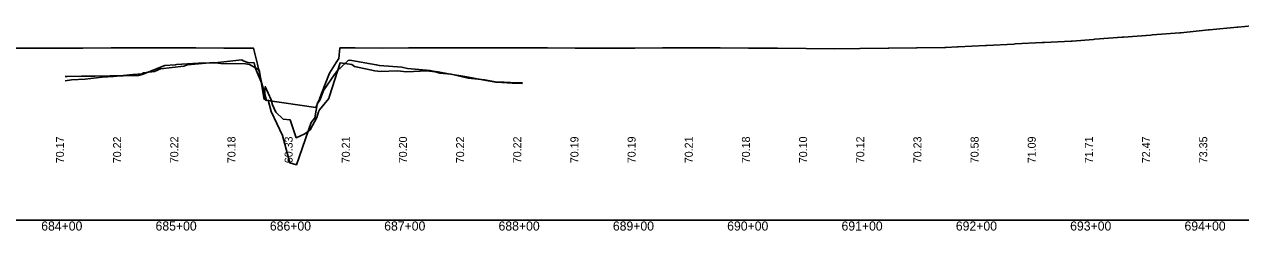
# Model space of a CAD drawing. Extents: x 2526761 to 2530854, y 882903 to 888012.
# Drawn here: x 2528703 to 2529767, y 887503 to 887684 of the extents above; entities that cross this region are included whole.
import ezdxf

# ---------------------------------------------------------------- set-up
doc = ezdxf.new("R2010")
doc.units = 0
for name, color, linetype in [('RD_DDB_Profile_EX', 7, 'Continuous'), ('RD_DDB_StaTX', 7, 'Continuous'), ('RD_DDB_StripGrade', 7, 'Continuous'), ('RD_GPK_Profile_Cell', 7, 'Continuous')]:
    doc.layers.add(name, color=color, linetype=linetype)

msp = doc.modelspace()

# ---------------------------------------------------------------- linework, layer by layer
at = {"layer": 'RD_DDB_Profile_EX'}
for points in [[(2529311.6, 887663.2), (2529312.1, 887663.2), (2529336.7, 887663), (2529337.1, 887663), (2529361.8, 887662.8), (2529362.1, 887662.8), (2529387.1, 887662.6), (2529412.1, 887662.4), (2529434.1, 887662.6), (2529434.4, 887662.6), (2529458.9, 887662.9), (2529459.4, 887662.9), (2529483.8, 887663.2), (2529484.4, 887663.2), (2529508.6, 887663.4), (2529509.4, 887663.5), (2529519.6, 887664), (2529520.1, 887664), (2529544, 887665.2), (2529545.1, 887665.3), (2529568.9, 887666.5), (2529570.1, 887666.6), (2529593.7, 887667.8), (2529595.2, 887667.9), (2529595.7, 887667.9), (2529619.1, 887669.1), (2529619.9, 887669.2), (2529638.5, 887670.6), (2529639.8, 887670.7), (2529663.5, 887672.5), (2529664.7, 887672.6), (2529688.8, 887674.4), (2529689.7, 887674.5), (2529714, 887676.4), (2529714.9, 887676.4), (2529739.2, 887678.9), (2529739.9, 887678.9), (2529764.3, 887681.4), (2529764.9, 887681.4), (2529789.3, 887683.8)], [(2528687.5, 887662.8), (2528711.7, 887662.8), (2528712.5, 887662.8), (2528729.2, 887662.9), (2528729.6, 887662.9), (2528754.2, 887663), (2528754.6, 887663), (2528779.3, 887663.1), (2528779.6, 887663.1), (2528804.6, 887663.3), (2528823.4, 887663.2), (2528828.4, 887663.2), (2528853.4, 887663.1), (2528877.9, 887663), (2528878.4, 887663), (2528902.7, 887662.9), (2528903.4, 887662.9), (2528903.7, 887663), (2528907.2, 887649), (2528908.2, 887644.7), (2528910, 887637.3), (2528914.2, 887617.5), (2528958.2, 887610.8), (2528961.5, 887618.3), (2528963.4, 887623.2), (2528970.2, 887640.9), (2528976.2, 887650.3), (2528978.5, 887653.8), (2528979.3, 887663.2), (2528979.6, 887663.2), (2528980.2, 887663.2), (2528991.2, 887663.1), (2528992.6, 887663.1), (2529016.3, 887663), (2529039.5, 887663.1), (2529040.4, 887663.1), (2529064.6, 887663.1), (2529065.4, 887663.1), (2529089.7, 887663.2), (2529090.4, 887663.2), (2529114.8, 887663.2), (2529115.4, 887663.2), (2529135.4, 887663.2), (2529136, 887663.2), (2529160.2, 887663.1), (2529161, 887663.1), (2529185.2, 887663), (2529186, 887663), (2529210.1, 887663), (2529211, 887662.9), (2529211.6, 887663), (2529212.5, 887663), (2529236.6, 887663), (2529237.4, 887663), (2529261.6, 887663.1), (2529262.3, 887663.1), (2529286.6, 887663.1), (2529287.2, 887663.1), (2529311.6, 887663.2)], [(2528739, 887634.4), (2528744.7, 887635.1), (2528756.4, 887635.7), (2528771.5, 887637.4), (2528781.3, 887638), (2528798.3, 887639.9), (2528806.2, 887640.4), (2528807.6, 887641.2), (2528817.2, 887642.4), (2528822.4, 887644.9), (2528842.9, 887647.1), (2528846, 887648.3), (2528868.4, 887650.4), (2528870.1, 887650.1), (2528893.6, 887652.6), (2528894.7, 887651.8), (2528898.7, 887650.5), (2528904.3, 887650.1), (2528905.6, 887645.1), (2528911.1, 887632.1), (2528913.5, 887623.7), (2528915.2, 887617), (2528916.7, 887617.3), (2528919.3, 887607.4), (2528929, 887586.3), (2528935.5, 887562.4), (2528941.3, 887560.8), (2528954.1, 887597.7), (2528957.3, 887602), (2528959.8, 887615.2), (2528961.3, 887616.2), (2528962.2, 887618), (2528965.1, 887625.9), (2528974.6, 887639.9), (2528978.3, 887644.8), (2528979.2, 887645), (2528986.7, 887652), (2528988.1, 887652.4), (2529011.1, 887648.4), (2529013.9, 887647.7), (2529033.5, 887646.3), (2529038.5, 887645), (2529058.2, 887643.4), (2529060.9, 887642.9), (2529065.4, 887642.1), (2529074.3, 887640.5), (2529090.5, 887637.7), (2529104.1, 887635.1), (2529115.6, 887633), (2529123.1, 887633), (2529134.1, 887632.6), (2529139, 887632.5)], [(2528739, 887638.1), (2528740.7, 887638.1), (2528753.2, 887638.5), (2528765.2, 887638.3), (2528778.2, 887638.7), (2528789.8, 887638.6), (2528803.3, 887639), (2528806.3, 887639.9), (2528826.2, 887647.7), (2528835.4, 887648.2), (2528836.3, 887648.5), (2528860.2, 887650.2), (2528872.9, 887649.9), (2528875.1, 887649.6), (2528896.8, 887649.1), (2528900.3, 887648.6), (2528907.7, 887644.6), (2528908.7, 887643.8), (2528913.2, 887618), (2528914.1, 887629.2), (2528919.2, 887617.7), (2528920.4, 887613.2), (2528923.4, 887606.7), (2528929.8, 887600.6), (2528935.8, 887600.2), (2528941.1, 887584.4), (2528948.7, 887587.8), (2528953.2, 887591.4), (2528959.2, 887602.2), (2528960.5, 887607.1), (2528961.4, 887609), (2528969.7, 887618.9), (2528970.4, 887621), (2528979.5, 887650), (2528989.8, 887648.7), (2528992, 887646.9), (2529010, 887643), (2529015.3, 887642.5), (2529029.5, 887643), (2529038, 887642.2), (2529055.3, 887643), (2529062.8, 887642.2), (2529066.8, 887641.1), (2529076.7, 887640.1), (2529091.6, 887636.5), (2529106, 887635.3), (2529116.5, 887633.1), (2529130, 887632.2), (2529136.2, 887632.3), (2529139, 887632.1)]]:
    msp.add_lwpolyline(points, dxfattribs=at)
at = {"layer": 'RD_GPK_Profile_Cell'}
msp.add_line((2526839, 887512.1), (2530839, 887512.1), dxfattribs=at)

# ---------------------------------------------------------------- texts
at = {"layer": 'RD_DDB_StaTX'}
for s, p in [('684+00', (2528718.1, 887503.1)), ('685+00', (2528818.1, 887503.1)), ('686+00', (2528918.1, 887503.1)), ('687+00', (2529018.1, 887503.1)), ('688+00', (2529118.1, 887503.1)), ('689+00', (2529218.1, 887503.1)), ('690+00', (2529318.1, 887503.1)), ('691+00', (2529418.1, 887503.1)), ('692+00', (2529518.1, 887503.1)), ('693+00', (2529618.1, 887503.1)), ('694+00', (2529718.1, 887503.1))]:
    msp.add_text(s, height=8, dxfattribs=at).set_placement(p)
at = {"layer": 'RD_DDB_StripGrade'}
for s, p in [('70.17', (2528738, 887562.1)), ('70.22', (2528788, 887562.1)), ('70.22', (2528838, 887562.1)), ('70.18', (2528888, 887562.1)), ('60.33', (2528938, 887562.1)), ('70.21', (2528988, 887562.1)), ('70.20', (2529038, 887562.1)), ('70.22', (2529088, 887562.1)), ('70.22', (2529138, 887562.1)), ('70.19', (2529188, 887562.1)), ('70.19', (2529238, 887562.1)), ('70.21', (2529288, 887562.1)), ('70.18', (2529338, 887562.1)), ('70.10', (2529388, 887562.1)), ('70.12', (2529438, 887562.1)), ('70.23', (2529488, 887562.1)), ('70.58', (2529538, 887562.1)), ('71.09', (2529588, 887562.1)), ('71.71', (2529638, 887562.1)), ('72.47', (2529688, 887562.1)), ('73.35', (2529738, 887562.1))]:
    msp.add_text(s, height=7, rotation=90, dxfattribs=at).set_placement(p)

doc.saveas('drawing.dxf')
